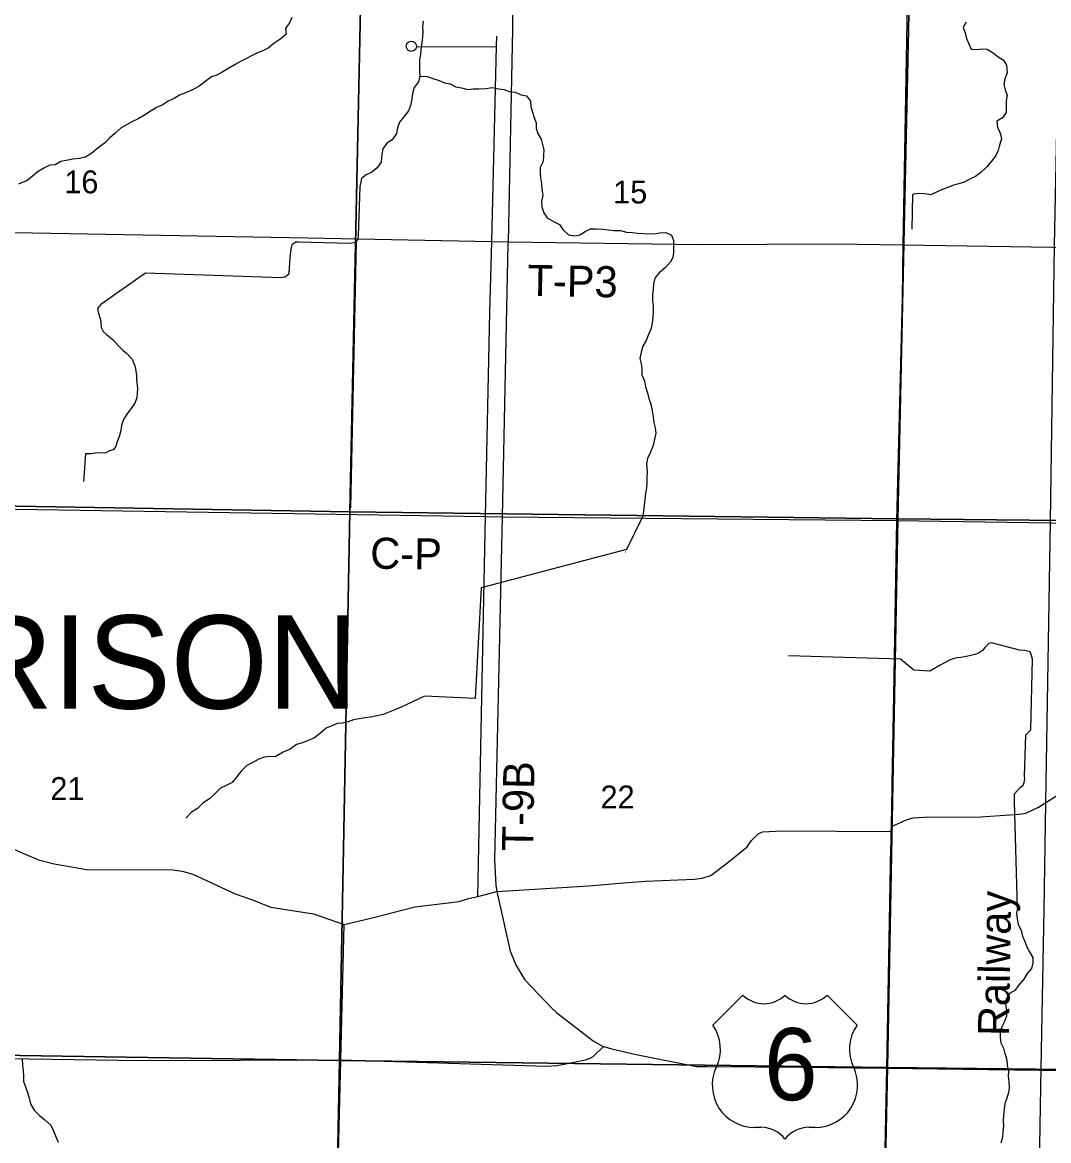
# Model space of a CAD drawing. Extents: x -6.2 to 37.4, y 0.2 to 22.2.
# Drawn here: x 4.101 to 5.038, y 16.289 to 17.311 of the extents above; entities that cross this region are included whole.
import ezdxf

# ---------------------------------------------------------------- set-up
doc = ezdxf.new("R2010")
doc.units = 0
for name, color, linetype in [('GM_X_County_Road', 7, 'Continuous'), ('GM_X_County_Road_Text', 7, 'Continuous'), ('GM_X_Minor_River', 7, 'Continuous'), ('GM_X_Rail_Line', 7, 'Continuous'), ('GM_X_Rail_Line_Text', 7, 'Continuous'), ('GM_X_Section', 7, 'Continuous'), ('GM_X_Section_Text', 7, 'Continuous'), ('GM_X_State_Route', 7, 'Continuous'), ('GM_X_Township_Road', 7, 'Continuous'), ('GM_X_Township_Road_Text', 7, 'Continuous'), ('GM_X_Township_Text', 7, 'Continuous'), ('GM_X_US_Route', 7, 'Continuous'), ('GM_X_US_Shield', 7, 'Continuous')]:
    doc.layers.add(name, color=color, linetype=linetype)

msp = doc.modelspace()

# ---------------------------------------------------------------- linework, layer by layer
at = {"layer": 'GM_X_County_Road'}
for points in [[(3.0857, 16.8847), (3.1487, 16.8834), (3.2649, 16.8811), (3.3987, 16.8787), (3.6901, 16.8729), (3.9588, 16.8683), (4.5241, 16.8594)], [(4.5241, 16.8594), (4.5391, 16.8592), (4.8996, 16.8558), (5.0809, 16.853)], [(3.458, 16.3725), (3.8696, 16.3674), (3.8844, 16.3672), (4.209, 16.3625), (4.392, 16.3629), (4.5795, 16.3571), (4.5894, 16.3579), (4.6034, 16.3606), (4.6154, 16.3629), (4.6196, 16.3644), (4.6223, 16.366), (4.6318, 16.3752)]]:
    msp.add_lwpolyline(points, dxfattribs=at)
at = {"layer": 'GM_X_Minor_River'}
for points in [[(4.3471, 17.3155), (4.345, 17.3106), (4.3413, 17.3058), (4.3421, 17.3003), (4.3363, 17.2954), (4.3307, 17.2916), (4.3257, 17.2873), (4.3208, 17.2851), (4.3158, 17.2833), (4.311, 17.2806), (4.3059, 17.278), (4.3009, 17.2755), (4.2953, 17.2726), (4.2896, 17.2693), (4.2836, 17.2654), (4.2787, 17.2629), (4.2737, 17.2611), (4.2678, 17.2568), (4.2627, 17.2526), (4.2559, 17.2491), (4.2501, 17.2467), (4.2446, 17.2446), (4.2396, 17.2415), (4.2341, 17.2389), (4.2289, 17.2354), (4.2235, 17.2331), (4.2186, 17.2303), (4.2126, 17.2263), (4.2067, 17.2228), (4.2011, 17.22), (4.1961, 17.2173), (4.1914, 17.2147), (4.1858, 17.2097), (4.1809, 17.2055), (4.1761, 17.2006), (4.1703, 17.1964), (4.1644, 17.1916), (4.1588, 17.1879), (4.1531, 17.1867), (4.1472, 17.1859), (4.1425, 17.1852), (4.1362, 17.1838), (4.131, 17.1809), (4.1263, 17.1804), (4.1208, 17.1779), (4.1154, 17.1746), (4.1104, 17.1705), (4.1056, 17.1664), (4.0977, 17.1633)], [(4.4671, 17.3121), (4.4666, 17.307), (4.4667, 17.3023), (4.4666, 17.2975), (4.4659, 17.2926), (4.465, 17.2866), (4.4647, 17.2816), (4.4637, 17.2767), (4.4638, 17.2718), (4.4637, 17.2671), (4.4641, 17.2619), (4.4629, 17.2568), (4.459, 17.2514), (4.4575, 17.2461), (4.4567, 17.2408), (4.4554, 17.2352), (4.4536, 17.2303), (4.4493, 17.2247), (4.4454, 17.2198), (4.4436, 17.2147), (4.4428, 17.2094), (4.4387, 17.2036), (4.4339, 17.2007), (4.4304, 17.1955), (4.4293, 17.1905), (4.4286, 17.1832), (4.4251, 17.1781), (4.4201, 17.174), (4.4151, 17.1717), (4.4109, 17.1684), (4.4094, 17.1608)], [(4.9629, 17.3111), (4.9602, 17.3062), (4.9621, 17.3014), (4.9632, 17.2963), (4.9653, 17.2915), (4.9675, 17.2865), (4.9726, 17.2862), (4.9773, 17.2867), (4.9823, 17.2864), (4.9875, 17.2831), (4.9923, 17.2795), (4.9972, 17.2766), (4.9997, 17.2718), (5.0004, 17.2648), (4.9982, 17.2595), (4.9973, 17.2542), (4.9985, 17.2493), (5.0003, 17.2443), (4.9994, 17.2392), (4.9995, 17.2341), (4.9996, 17.2287), (4.9963, 17.2239), (4.9911, 17.2206), (4.9917, 17.2152), (4.9939, 17.2097), (4.9951, 17.2046), (4.9935, 17.1989), (4.9921, 17.194), (4.9899, 17.1889), (4.986, 17.1841), (4.9819, 17.179), (4.9763, 17.1738), (4.9715, 17.1701), (4.9663, 17.1678), (4.9612, 17.165), (4.9562, 17.1634), (4.9513, 17.1622), (4.9463, 17.16), (4.941, 17.1582), (4.9352, 17.1555), (4.9305, 17.1533), (4.925, 17.1544), (4.9201, 17.1545), (4.9151, 17.154), (4.914, 17.1534)], [(4.4641, 17.2619), (4.4709, 17.2614), (4.4758, 17.2598), (4.4816, 17.2578), (4.4865, 17.2558), (4.4918, 17.2547), (4.4968, 17.252), (4.5021, 17.2513), (4.5078, 17.2498), (4.5129, 17.2503), (4.5178, 17.2502), (4.5246, 17.2505), (4.5301, 17.2515), (4.5358, 17.2504), (4.5407, 17.2498), (4.5458, 17.2478), (4.5511, 17.2471), (4.5567, 17.2447), (4.5616, 17.2438), (4.5651, 17.239), (4.5653, 17.2337), (4.567, 17.2289), (4.5686, 17.224), (4.5702, 17.2192), (4.5704, 17.2144), (4.5718, 17.2095), (4.575, 17.2043), (4.576, 17.1993), (4.5774, 17.1946), (4.5771, 17.1896), (4.5766, 17.1838), (4.5738, 17.1785), (4.5741, 17.1736), (4.5742, 17.1688), (4.5752, 17.1635), (4.5755, 17.1587), (4.5763, 17.1532), (4.5751, 17.1474), (4.5756, 17.1424), (4.5773, 17.1371), (4.5804, 17.1323), (4.5866, 17.1287), (4.5915, 17.1264), (4.5948, 17.1216), (4.5998, 17.1169), (4.6055, 17.1158), (4.6102, 17.1169), (4.615, 17.12), (4.6198, 17.1224), (4.6251, 17.1225), (4.6308, 17.122), (4.6361, 17.1215), (4.6415, 17.1208), (4.6472, 17.1207), (4.6527, 17.1194), (4.658, 17.119), (4.6631, 17.1183), (4.6683, 17.118), (4.6784, 17.1178), (4.6831, 17.1186), (4.6888, 17.1189), (4.6939, 17.1167), (4.6957, 17.1117), (4.6957, 17.1068), (4.6958, 17.1021), (4.6955, 17.0969), (4.693, 17.0921), (4.6883, 17.087), (4.6827, 17.0822), (4.6787, 17.0772), (4.6774, 17.0721), (4.6771, 17.0668), (4.6766, 17.0617), (4.6765, 17.0569), (4.6772, 17.052), (4.6771, 17.0465), (4.6768, 17.0416), (4.6763, 17.0361), (4.675, 17.0308), (4.673, 17.0257), (4.6708, 17.0202), (4.6677, 17.015), (4.6661, 17.0095), (4.665, 17.004), (4.6661, 16.9991), (4.6667, 16.9943), (4.6668, 16.9888), (4.6691, 16.9835), (4.6702, 16.9779), (4.6719, 16.9724), (4.6733, 16.9673), (4.6751, 16.9621), (4.6763, 16.956), (4.6771, 16.9505), (4.6778, 16.9455), (4.679, 16.9406), (4.6795, 16.9356), (4.6784, 16.9298), (4.6772, 16.9245), (4.6746, 16.9183), (4.672, 16.9126)], [(4.4094, 17.1608), (4.4077, 17.1159), (4.4073, 17.1135), (4.4059, 17.1102), (4.4036, 17.1095), (4.4005, 17.109), (4.3531, 17.1103), (4.3508, 17.1102), (4.3473, 17.1078), (4.3463, 17.1042), (4.3454, 17.0955), (4.3445, 17.0821), (4.3441, 17.0807), (4.3409, 17.0782), (4.3373, 17.0777), (4.2136, 17.0817), (4.1728, 17.0533), (4.1697, 17.0496), (4.1704, 17.0462), (4.172, 17.0404), (4.1729, 17.0372), (4.1732, 17.0321), (4.175, 17.0286), (4.178, 17.0257), (4.1839, 17.021), (4.1885, 17.0158), (4.193, 17.0112), (4.196, 17.009), (4.2015, 17.0032), (4.204, 16.9961), (4.2052, 16.9883), (4.2053, 16.9849), (4.2063, 16.9766), (4.2055, 16.9679), (4.2039, 16.963), (4.2008, 16.9588), (4.1965, 16.9531), (4.1936, 16.9482), (4.1917, 16.9425), (4.1909, 16.9382), (4.1898, 16.9335), (4.1874, 16.9267), (4.1866, 16.9235), (4.1839, 16.9205), (4.1807, 16.9194), (4.1774, 16.9178), (4.1677, 16.9174), (4.1638, 16.9167), (4.1605, 16.9168), (4.1586, 16.9168), (4.157, 16.8914)], [(4.914, 17.1534), (4.9135, 17.122)], [(4.4059, 17.1102), (4.4008, 16.8675)], [(4.672, 16.9126), (4.6711, 16.9077), (4.6718, 16.9007), (4.6713, 16.8956), (4.6715, 16.8907), (4.6711, 16.8857), (4.6702, 16.8804), (4.6695, 16.8753), (4.669, 16.8698), (4.6683, 16.864), (4.6673, 16.8591)], [(4.6673, 16.8591), (4.6527, 16.8294), (4.5202, 16.7943), (4.5147, 16.6931), (4.4684, 16.6952), (4.4521, 16.6876)], [(4.6519, 16.8271), (4.6521, 16.8273)], [(5.0098, 16.5016), (5.0071, 16.5992), (5.0072, 16.6062), (5.0123, 16.6118), (5.0151, 16.614), (5.0158, 16.6164), (5.0164, 16.6197), (5.0163, 16.6221), (5.0174, 16.6599), (5.0219, 16.6645), (5.0234, 16.729), (5.0225, 16.7326), (5.0215, 16.7357), (5.0164, 16.7369), (5.0117, 16.7372), (4.9861, 16.744), (4.9838, 16.7434), (4.9799, 16.7397), (4.978, 16.7369), (4.9741, 16.7345), (4.9709, 16.7333), (4.9671, 16.7326), (4.9631, 16.7317), (4.9582, 16.7307), (4.9549, 16.7302), (4.9511, 16.7293), (4.9479, 16.7282), (4.9393, 16.7235), (4.9297, 16.7181), (4.9151, 16.7192), (4.903, 16.7291), (4.8007, 16.7321)], [(4.4521, 16.6876), (4.4471, 16.6854), (4.4418, 16.683), (4.4368, 16.681), (4.4305, 16.6787), (4.4191, 16.6761), (4.4142, 16.6756), (4.4087, 16.6746), (4.4036, 16.6736), (4.3986, 16.6718), (4.3933, 16.6707), (4.3885, 16.6703), (4.3832, 16.6679), (4.3784, 16.6661), (4.3736, 16.6618), (4.368, 16.6572), (4.3621, 16.6549), (4.3569, 16.6527), (4.3514, 16.6511), (4.3457, 16.6469), (4.3392, 16.644), (4.3319, 16.6399), (4.326, 16.6401), (4.3211, 16.6392), (4.3163, 16.6374), (4.3111, 16.6345), (4.3062, 16.6319), (4.301, 16.6267), (4.2965, 16.6213), (4.2926, 16.6165), (4.2871, 16.6137), (4.2819, 16.6112), (4.2767, 16.6058), (4.2719, 16.6015), (4.2661, 16.5977), (4.2609, 16.5926), (4.2555, 16.5893), (4.2509, 16.5845), (4.2505, 16.5839)], [(5.0098, 16.5016), (5.009, 16.4969), (5.0096, 16.4919), (5.0106, 16.4868), (5.0133, 16.4814), (5.0143, 16.4761), (5.0164, 16.4712), (5.0184, 16.4664), (5.0209, 16.4616), (5.0237, 16.4566), (5.024, 16.4517), (5.0225, 16.4466), (5.0186, 16.4418), (5.0156, 16.4367), (5.0114, 16.4317), (5.0073, 16.4265), (5.0025, 16.4235), (4.9995, 16.4186), (4.9989, 16.4135), (4.9997, 16.4084), (4.9998, 16.403), (4.9981, 16.398), (4.9955, 16.3931), (4.994, 16.3882), (4.9939, 16.3833), (4.9945, 16.3785), (4.997, 16.3737), (4.9983, 16.3687), (5.0001, 16.363), (5.0005, 16.3579), (5.0015, 16.3529), (5.0013, 16.348), (5.0019, 16.3432), (5.0022, 16.3379), (5.0016, 16.333), (5.0002, 16.3281), (4.9983, 16.3232), (4.9978, 16.3179), (4.997, 16.3124), (4.9969, 16.3073), (4.9971, 16.3026), (4.9964, 16.2973), (4.9962, 16.2923), (4.9946, 16.2867)], [(4.1008, 16.3639), (4.1011, 16.358), (4.1018, 16.3533), (4.102, 16.348), (4.1022, 16.3432), (4.104, 16.3384), (4.1057, 16.333), (4.1073, 16.3281), (4.1084, 16.3229), (4.1119, 16.3171), (4.1168, 16.3122), (4.1216, 16.3081), (4.127, 16.3034), (4.1293, 16.2986), (4.1313, 16.2936), (4.1337, 16.2878)]]:
    msp.add_lwpolyline(points, dxfattribs=at)
at = {"layer": 'GM_X_Rail_Line'}
msp.add_lwpolyline([(5.0025, 14.3074), (5.0025, 14.3335), (5.0039, 14.639), (5.0028, 14.7258), (5.0054, 14.9018), (5.0142, 15.3507), (5.0314, 16.3553), (5.0343, 16.5004), (5.0358, 16.5978), (5.0401, 16.8553), (5.0435, 17.1071), (5.0536, 17.6004), (5.0579, 17.8816), (5.0677, 18.5001), (5.0692, 18.5857), (5.0746, 18.8476), (5.0809, 19.3027)], dxfattribs=at)
at = {"layer": 'GM_X_Section'}
for points in [[(3.9091, 17.3739), (4.4109, 17.3678), (4.4001, 16.8637), (3.8978, 16.8723)], [(4.4109, 17.3678), (4.9115, 17.3605), (4.9005, 16.8573), (4.4001, 16.8637)], [(4.4001, 16.8637), (4.3906, 16.3625), (3.8845, 16.3704), (3.8978, 16.8723)], [(4.9005, 16.8573), (4.8912, 16.3559), (4.3906, 16.3625), (4.4001, 16.8637)], [(4.3906, 16.3625), (4.3809, 15.8604), (3.8735, 15.8683), (3.8845, 16.3704)], [(4.8912, 16.3559), (4.8806, 15.8553), (4.3809, 15.8604), (4.3906, 16.3625)]]:
    msp.add_lwpolyline(points, close=True, dxfattribs=at)
for points in [[(5.0809, 16.8554), (4.9005, 16.8573), (4.9115, 17.3605), (5.0809, 17.3581)], [(5.0809, 16.3538), (4.8912, 16.3559), (4.9005, 16.8573), (5.0809, 16.8554)], [(5.0809, 15.8527), (4.8806, 15.8553), (4.8912, 16.3559), (5.0809, 16.3538)]]:
    msp.add_lwpolyline(points, dxfattribs=at)
at = {"layer": 'GM_X_State_Route'}
for p, q in [((4.8947, 16.5761), (4.8953, 16.6124)), ((4.8946, 16.5715), (4.8947, 16.5761)), ((4.8906, 16.3555), (4.8943, 16.557))]:
    msp.add_line(p, q, dxfattribs=at)
for points in [[(4.8953, 16.6124), (4.8954, 16.6154), (4.8969, 16.6959), (4.8996, 16.8558), (4.9047, 17.0594), (4.9055, 17.1076), (4.9112, 17.4312), (4.9179, 17.5894)], [(4.8943, 16.557), (4.8944, 16.5604), (4.8946, 16.5715)], [(4.8816, 15.3526), (4.8801, 15.3594), (4.8777, 15.3641), (4.8752, 15.3685), (4.8737, 15.374), (4.8731, 15.3856), (4.8802, 15.8524), (4.8854, 16.1035), (4.8906, 16.3555)]]:
    msp.add_lwpolyline(points, dxfattribs=at)
at = {"layer": 'GM_X_Township_Road'}
for p, q in [((4.9055, 17.1076), (5.0809, 17.1051)), ((4.8946, 16.5715), (4.8947, 16.5761)), ((4.392, 16.3629), (4.395, 16.4868))]:
    msp.add_line(p, q, dxfattribs=at)
for points in [[(4.4613, 17.2887), (4.4597, 17.2859), (4.4583, 17.2849), (4.456, 17.2845), (4.4544, 17.2849), (4.4532, 17.2857), (4.4521, 17.2873), (4.4516, 17.2886), (4.4518, 17.2904), (4.4526, 17.2922), (4.4541, 17.2933), (4.456, 17.2939), (4.4581, 17.2935), (4.4597, 17.2924), (4.4608, 17.2906), (4.4613, 17.2887), (4.5342, 17.2889)], [(4.5297, 17.1107), (4.5342, 17.2889), (4.5344, 17.2985)], [(3.4085, 17.1308), (3.8585, 17.1234), (4.3619, 17.1141), (4.5297, 17.1107), (4.5446, 17.1104)], [(4.517, 16.5123), (4.5218, 16.7546), (4.5241, 16.8594), (4.5281, 17.0459), (4.5297, 17.1107)], [(4.5446, 17.1104), (4.7192, 17.1079), (4.8428, 17.1085), (4.9055, 17.1076)], [(4.8947, 16.5761), (4.909, 16.5825), (4.9145, 16.584), (4.9249, 16.5846), (4.9765, 16.585), (5.0118, 16.5876), (5.0176, 16.5883), (5.0291, 16.5938), (5.0809, 16.6264)], [(3.9789, 16.6066), (4.1015, 16.5518), (4.1157, 16.5459), (4.13, 16.5421), (4.144, 16.5397), (4.1597, 16.5368), (4.2386, 16.5366), (4.2469, 16.5354), (4.2569, 16.5326), (4.2953, 16.5148), (4.3102, 16.5095), (4.3279, 16.5026), (4.367, 16.4964), (4.395, 16.4868), (4.4205, 16.4927), (4.4596, 16.5029), (4.5001, 16.5078), (4.5086, 16.5103), (4.517, 16.5123), (4.5344, 16.5169)], [(4.5344, 16.5169), (4.6185, 16.5219), (4.65, 16.5247), (4.67, 16.5262), (4.7149, 16.5282), (4.7215, 16.5289), (4.7297, 16.5314), (4.7452, 16.5432), (4.7629, 16.5576), (4.7669, 16.5634), (4.7729, 16.5696), (4.7769, 16.5712), (4.7949, 16.5721), (4.8946, 16.5715)], [(4.3799, 15.8573), (4.3855, 16.1068), (4.392, 16.3629)]]:
    msp.add_lwpolyline(points, dxfattribs=at)
at = {"layer": 'GM_X_US_Route'}
for p, q in [((4.8607, 16.3558), (4.8906, 16.3555)), ((4.8906, 16.3555), (5.0298, 16.3536)), ((5.0298, 16.3536), (5.0809, 16.3529))]:
    msp.add_line(p, q, dxfattribs=at)
for points in [[(4.5483, 17.3235), (4.5486, 17.3136), (4.5488, 17.3047), (4.5446, 17.1104), (4.5445, 17.1087), (4.5391, 16.8592), (4.5323, 16.5457), (4.5334, 16.5225), (4.5344, 16.5169), (4.5465, 16.4624), (4.5521, 16.4491), (4.5599, 16.4361), (4.5849, 16.4098), (4.5893, 16.4059), (4.6223, 16.3803), (4.6303, 16.3757), (4.6318, 16.3752), (4.6394, 16.3731), (4.6615, 16.3678), (4.7166, 16.357), (4.7261, 16.3569)], [(4.7261, 16.3569), (4.8133, 16.3562), (4.8607, 16.3558)]]:
    msp.add_lwpolyline(points, dxfattribs=at)
at = {"layer": 'GM_X_US_Shield'}
for p, q in [((4.7591, 16.4222), (4.7316, 16.3947)), ((4.8634, 16.3947), (4.836, 16.4222)), ((4.77, 16.3014), (4.7755, 16.3014)), ((4.8195, 16.3014), (4.825, 16.3014))]:
    msp.add_line(p, q, dxfattribs=at)
for centre, radius, start, end in [((4.7783, 16.4418), 0.0275, 225.573, 314.427), ((4.8167, 16.4418), 0.0275, 225.573, 314.427), ((4.7001, 16.3727), 0.0385, 334.5471, 35.0009), ((4.8949, 16.3727), 0.0385, 144.9991, 205.4529), ((4.7696, 16.3398), 0.0385, 154.8319, 270.6383), ((4.8254, 16.3398), 0.0385, 269.3617, 25.1681), ((4.7755, 16.2739), 0.0275, 36.8699, 90), ((4.8195, 16.2739), 0.0275, 90, 143.1301)]:
    msp.add_arc(centre, radius, start, end, dxfattribs=at)

# ---------------------------------------------------------------- texts
at = {"layer": 'GM_X_County_Road_Text'}
msp.add_text('C-P', height=0.02841, rotation=359.1191, dxfattribs=at).set_placement((4.4186, 16.8119))
at = {"layer": 'GM_X_Rail_Line_Text'}
msp.add_text('Railway', height=0.02831, rotation=89.0728, dxfattribs=at).set_placement((5.002, 16.3846))
at = {"layer": 'GM_X_Section_Text'}
for s, p in [('16', (4.1394, 17.1548)), ('15', (4.6406, 17.1455)), ('21', (4.1266, 16.6004)), ('22', (4.6291, 16.5927))]:
    msp.add_text(s, height=0.02093, rotation=0, dxfattribs=at).set_placement(p)
at = {"layer": 'GM_X_Township_Road_Text'}
for s, rotation, p in [('T-P3', 358.9714, (4.5622, 17.0611)), ('T-9B', 89.0227, (4.5674, 16.5533))]:
    msp.add_text(s, height=0.02841, rotation=rotation, dxfattribs=at).set_placement(p)
at = {"layer": 'GM_X_Township_Text'}
msp.add_text('HARRISON', height=0.08523, rotation=0, dxfattribs=at).set_placement((3.806, 16.6839))
at = {"layer": 'GM_X_US_Shield'}
msp.add_text('6', height=0.0659, dxfattribs=at).set_placement((4.7783, 16.3261))

doc.saveas('drawing.dxf')
